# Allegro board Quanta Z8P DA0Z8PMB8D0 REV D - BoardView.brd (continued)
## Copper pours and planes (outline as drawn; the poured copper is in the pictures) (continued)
SY8288CSW on BOTTOM (solid shape): 141.53,80.83 141.56,80.81 141.58,80.78 141.58,80.16 141.78,80.16 141.78,80.78 141.79,80.81 141.83,80.83 141.97,80.83 142.02,80.78 142.02,79.89 141.87,79.74 141.87,79.15 142.68,78.34 144.23,78.34 144.39,78.19 144.39,76.03 143.98,75.62 139.56,75.62 139.18,76 139.18,79.05 139.33,79.2 140.14,79.2 140.3,79.35 140.3,79.71 141.41,80.83
TERM9 on TOP (solid shape): 41.85,109.03 41.85,106.68 38.98,103.81 27.01,103.81 26.69,104.13 26.69,105.41 27,105.72 31.15,105.72 31.17,105.7 31.18,105.69 31.53,105.43 31.89,105.67 31.9,105.69 31.95,105.72 32.4,105.72 32.45,105.69 32.45,105.67 32.81,105.43 33.16,105.67 33.17,105.69 33.22,105.72 37.33,105.72 37.64,106.03 37.64,106.15 37.64,106.16 37.64,108.57 37.64,108.57 37.64,108.77 38.13,109.27 41.6,109.27
TERM9 on BOTTOM (solid shape): 41.82,108.82 41.82,105.54 41.64,105.36 38.9,105.36 38.58,105.68 38.58,108.8 38.94,109.16 41.48,109.16
TP_PWR on BOTTOM (solid shape): 62.32,125.12 64.66,125.12 64.91,124.87 64.91,124.11 64.78,123.99 61.57,123.99 61.25,124.31 61.25,125.55 61.29,125.59 61.84,125.59
USBPWR1 on TOP (solid shape): 24.36,55.53 24.36,54.02 23.94,53.6 22.08,53.6 21.67,53.2 19.54,53.2 19.49,53.15 19.34,53.15 19.13,52.94 19.05,52.83 19.02,52.7 19.02,52.68 17.7,51.36 17.69,51.35 17.67,51.35 17.62,51.35 17.58,51.39 16.77,51.39 16.77,51.38 16.74,51.35 16.64,51.35 16.18,50.89 16.18,50.57 15.88,50.27 15.37,50.27 15.07,50.58 15.07,53.12 15.34,53.39 16.21,53.39 17.21,54.39 19.34,54.39 19.52,54.56 19.52,55.05 19.85,55.38 22.67,55.38 22.85,55.4 23,55.47 23.09,55.54 23.18,55.63 23.22,55.65 24.24,55.65
USBPWR1 on BOTTOM (solid shape): outline of 263 points within 14.93,48.78 23.42,58.01
USBPWR2 on TOP (solid shape): 226.88,18.55 226.88,17.53 226.88,17.51 226.86,17.49 226.86,16.87 226.84,16.84 226.81,16.82 225.08,16.82 224.43,16.17 224.43,15.48 223.67,14.72 221.95,14.72 221.68,14.99 221.68,15.61 221.71,15.68 221.78,15.71 222.16,16.09 221.78,16.47 221.71,16.5 221.68,16.57 221.68,16.89 221.73,17.04 221.73,17.19 221.73,18.09 221.91,18.27 222.66,18.27 222.69,18.24 224.21,18.24 225,19.03 226.4,19.03
USBPWR2 on BOTTOM (solid shape): 223.25,19.41 223.31,19.36 223.35,19.32 223.39,19.28 223.43,19.25 223.48,19.23 223.54,19.22 223.59,19.21 223.65,19.21 223.7,19.22 223.76,19.23 223.81,19.25 223.85,19.28 223.89,19.32 223.93,19.36 224.19,19.41 224.76,18.84 224.76,16.73 224.24,16.21 224.24,16.06 223.96,15.78 222.97,15.78 221.93,16.81 221.93,17.19 221.7,17.42 221.7,17.5 223.7,17.5 223.7,18.8 223.5,18.8 223.5,17.5 223.2,17.5 223.2,18.8 223,18.8 223,17.5 222.7,17.5 222.7,18.8 222.5,18.8 222.5,17.5 222.2,17.5 222.2,18.8 222,18.8 222,17.5 221.7,17.5 221.7,18.8 221.99,19.09 222.05,19.11 222.16,19.15 222.31,19.21 222.48,19.28 222.65,19.36 222.75,19.41
USBPWR2 on IN1 (solid shape): outline of 231 points within 214.77,15.96 224.83,18.21
VA1 on TOP (solid shape): 36.47,22.21 36.47,20.25 36.47,20.24 36.47,20.04 36.31,19.88 34.81,19.88 34.05,20.64 34.05,22.5 34.22,22.66 36.02,22.66
VA1 on TOP (solid shape): 233.29,44.49 233.29,43.27 232.93,42.92 231.7,42.92 231.23,42.45 231.23,39.37 231.03,39.17 229.6,39.17 228.69,38.26 223.3,38.26 222.72,38.84 222.72,42.31 222.8,42.44 222.88,42.59 223.05,42.75 228.59,42.75 228.97,43.13 228.97,44.02 229.58,44.63 233.15,44.63
VA1 on BOTTOM (solid shape): 233.3,44.47 233.3,40.1 232.52,39.32 229.75,39.32 228.51,38.08 223.35,38.08 222.52,38.92 222.52,42.04 222.55,42.08 222.61,42.15 222.66,42.23 222.79,42.42 222.9,42.62 222.92,42.64 222.95,42.65 224.83,42.65 225.06,42.42 225.15,42.42 225.17,42.4 227.34,42.4 227.37,42.42 227.52,42.42 229.88,44.79 232.99,44.79
VA1 on BOTTOM (solid shape): 199.92,40.45 199.99,40.42 200.02,40.35 200.07,40.14 200.24,39.97 200.24,39.94 200.24,39.79 200.24,39.79 200.24,38.47 200.22,38.46 199.77,38.46 199.43,38.8 198.33,38.8 198.16,38.64 198.16,38.59 198.14,38.57 198.14,37.57 198.15,37.55 198.16,37.53 198.46,37.23 198.46,36.76 198.36,36.66 197.57,36.66 197,37.23 197.01,37.65 197,37.69 197,38.27 197.01,38.31 197,38.38 197.02,38.42 197.06,38.43 197.44,38.81 197.06,39.2 197.02,39.21 197,39.25 197,39.79 197.67,40.45
VA1 on IN1 (solid shape): outline of 3494 points within 175.43,12.4 237.77,44.81
VA1 on IN2 (solid shape): outline of 2602 points within 33.8,12.34 181.14,26.17
VA2 on TOP (solid shape): outline of 139 points within 222.52,33.18 237.77,42.73
VA2 on IN2 (solid shape): 236.77,41.92 237.07,40.87 237.77,40.05 237.77,36.29 236.59,35.11 228.48,35.11 228.45,35.12 228.43,35.15 228.05,35.46 227.68,35.15 227.66,35.12 227.63,35.11 223.05,35.11 222.54,35.62 222.54,37.7 222.69,37.85 226.66,37.85 226.94,37.57 231.68,37.57 236.03,41.92
VA2 on IN3 (solid shape): 236.77,42.06 237.03,40.94 237.77,40.05 237.77,35.17 237.55,34.96 230.88,34.96 230.87,34.96 230.76,34.97 230.65,34.96 230.64,34.96 230.22,34.96 230.21,34.96 230.1,34.97 229.99,34.96 229.98,34.96 228.53,34.96 228.46,34.99 228.43,35.06 228.05,35.46 227.67,35.06 227.64,34.99 227.57,34.96 226.43,34.96 226.2,35.18 222.85,35.18 222.13,35.9 222.13,37.75 222.54,38.16 223.58,38.16 223.85,38.11 224.12,38.16 228.54,38.16 228.92,37.77 230.87,37.77 231.68,38.59 231.68,40.95 232.85,42.12 236.77,42.12
VOUT_BACKLIGHT on TOP (solid shape): 54.63,113.71 54.63,110.01 54.11,109.49 51.45,109.49 51.17,109.77 51.17,110.77 51.75,111.34 51.75,112.37 52.25,112.87 52.25,114.14 52.46,114.34 52.47,114.35 52.49,114.36 53.98,114.36
VOUT_BACKLIGHT on TOP (solid shape): 60.89,131.16 60.9,131.14 60.94,131.01 61.02,130.89 61.05,130.86 61.09,130.82 61.11,130.78 61.11,129.55 61.04,129.47 61.01,129.46 60.98,129.46 60.96,129.47 60.78,129.57 60.59,129.61 59.89,129.61 59.54,129.26 59.5,129.26 59.21,129.55 59.21,130.88 59.52,131.18 60.86,131.18
VOUT_BACKLIGHT on BOTTOM (solid shape): 61.07,130.78 61.07,129.85 61.06,129.82 61.02,129.8 60.26,129.8 60.26,129.6 61.02,129.6 61.06,129.59 61.07,129.55 61.07,129.37 61.02,129.32 61,129.3 60.98,129.3 60.26,129.3 60.26,129.29 58.93,129.29 58.76,129.46 58.76,130.65 59.04,130.93 60.92,130.93
VOUT_BACKLIGHT on IN3 (solid shape): outline of 367 points within 52.61,111.17 61.12,131.1
N20280006 on TOP (solid shape): 35.95,74.94 35.95,73.79 35.27,73.11 32.63,73.11 32.56,73.18 32.55,73.19 32.55,73.21 32.55,74.46 32.56,74.47 32.56,74.84 32.83,75.12 35.77,75.12
N22836684 on BOTTOM (solid shape): 126.83,103.92 127.72,103.92 127.82,103.81 127.82,103.33 127.65,103.15 125.87,103.15 125.79,103.23 125.79,103.92 125.92,104.04 126.71,104.04
N22836710 on BOTTOM (solid shape): 117.98,108.59 117.98,107.74 118.39,107.33 120.28,107.33 121.03,106.58 121.03,100.68 120.61,100.26 114.7,100.26 114.27,100.69 114.31,100.69 114.31,104.7 114.61,105.01 115.13,105.01 115.53,105.42 115.53,106.1 115.73,106.3 115.96,106.3 116.11,106.46 116.11,108.11 115.76,108.46 115.76,108.67 115.8,108.71 117.87,108.71
N22836724 on BOTTOM (solid shape): 130.08,106.74 130.08,106.1 130.29,105.9 131.48,105.9 131.84,106.25 132.29,106.25 132.43,106.14 132.44,106.12 132.45,106.1 132.45,101.63 132.17,101.35 128.41,101.35 128.18,101.58 128.18,102.44 128.41,102.67 129.5,102.67 129.6,102.77 129.6,105.03 129.02,105.62 129.02,106.35 129.03,106.38 129.07,106.4 129.73,106.4 129.73,106.64 129.07,106.64 129.03,106.66 129.02,106.69 129.02,106.85 129.03,106.87 129.05,106.88 129.07,106.89 129.93,106.89
N22841416 on BOTTOM (solid shape): 91.25,135.26 91.25,127.51 90.69,126.95 86.5,126.95 85.03,128.43 85.03,135.34 85.15,135.46 91.05,135.46
N22841457 on TOP (solid shape): 98.67,133.2 98.67,132.62 98.31,132.26 96.63,132.26 96.51,132.39 96.51,133.18 97.27,133.94 97.93,133.94
N22841539 on BOTTOM (solid shape): 75.45,134.52 75.45,133.74 75.75,133.43 77.2,133.43 77.71,132.92 77.71,131.2 77.33,130.82 74.08,130.82 73.93,130.66 69.55,130.66 69.43,130.81 69.25,130.89 68.54,131.6 68.54,132.31 68.54,132.31 68.54,133.91 68.87,134.24 72.6,134.24 72.96,134.6 74.05,134.6 74.46,135.01 74.97,135.01
N22946208 on BOTTOM (solid shape): 92.14,137.29 92.14,136.94 92.51,136.57 92.51,134.16 92.44,134.09 91.68,134.09 91.5,134.27 91.5,137.47 91.53,137.5 91.93,137.5
N22946324 on BOTTOM (solid shape): 92.92,129.55 92.92,128.38 92.75,128.2 91.76,128.2 91.63,128.33 91.63,129.52 91.81,129.7 92.77,129.7
N22946324 on BOTTOM (solid shape): 94.87,135.29 94.89,135.28 94.92,135.26 95.42,135.26 95.46,135.21 95.46,134.19 95.34,134.07 94.45,134.07 94.02,134.5 94.02,135.08 94.2,135.26 94.6,135.26 94.67,135.27 94.74,135.29
N22950763 on TOP (solid shape): 74.66,127.94 74.66,126.12 74.59,126.04 73.93,126.04 73.75,126.22 73.75,127.92 73.85,128.02 74.59,128.02
N22950767 on BOTTOM (solid shape): 79.39,134.52 79.39,133.63 79.16,133.41 78.09,133.41 77.81,133.69 76.01,133.69 75.73,133.96 75.73,134.52 75.83,134.63 79.28,134.63
N22950844 on BOTTOM (solid shape): 75.09,130.43 75.09,129.42 74.95,129.27 74.88,129.27 74.13,129.27 73.88,129.52 73.88,129.82 73.6,130.1 73.6,130.31 73.75,130.46 75.07,130.46
N23063584 on TOP (solid shape): 53.17,125.38 53.21,125.37 53.22,125.33 53.22,124.52 53.27,124.52 53.3,124.51 53.32,124.47 53.32,124.39 53.41,124.29 53.41,124.05 53.92,123.55 55.09,123.55 55.88,122.77 57.07,122.77 57.36,123.05 57.36,123.39 57.54,123.58 58.19,123.58 58.48,123.3 58.87,123.3 59,123.17 59,122.64 58.53,122.18 58.53,118.93 59.03,118.43 59.03,117.21 58.85,117.03 56.65,117.03 56.24,117.44 52.71,117.44 52.45,117.7 52.45,118.63 52.86,119.04 52.86,124.09 52.87,124.11 52.87,124.47 52.89,124.51 52.92,124.52 52.95,124.52 52.95,125.33 52.96,125.37 53,125.38
N25421357 on BOTTOM (solid shape): 200.24,37.76 200.24,35.74 200.12,35.62 198.71,35.62 198.61,35.72 198.61,37.27 198.26,37.62 198.26,38.52 198.34,38.6 199.4,38.6
N25421386 on TOP (solid shape): 62.23,19.87 62.23,16.57 61.99,16.33 61.47,16.33 61.25,16.11 61.25,14.18 60.72,13.64 54.27,13.64 53.55,14.36 53.55,17.43 54.06,17.94 58.17,17.94 60.27,20.04 62.06,20.04
N25421386 on BOTTOM (solid shape): 61.25,17.63 61.25,14.18 60.72,13.64 54.27,13.64 53.55,14.36 53.55,17.43 54.06,17.94 60.95,17.94
N25421433 on TOP (solid shape): 57.78,21.08 57.78,20.16 57.59,19.96 55.11,19.96 54.85,20.22 54.85,21.11 55,21.26 57.6,21.26
N25421470 on TOP (solid shape): 222.72,35.34 226.17,35.34 226.6,34.9 226.6,30.08 226.22,29.7 221.73,29.7 220.94,30.49 220.94,32.34 220.66,32.62 220.15,32.62 219.95,32.82 219.95,35.79 220.18,36.02 222.03,36.02
N25421528 on TOP (solid shape): 39.82,23.28 39.86,23.27 39.87,23.23 39.87,22.68 39.79,22.6 39.75,22.6 39.7,22.61 39.67,22.62 39.37,22.62 39.33,22.61 39.28,22.6 38.88,22.6 38.19,21.91 38.19,20.39 38.12,20.28 38.09,20.15 38.09,20.1 38.1,20.05 38.1,20.03 38.08,20.01 37.97,19.9 37.05,19.9 37.01,19.92 37,19.92 36.94,19.99 36.86,20.04 36.59,20.3 36.59,22.57 37.31,23.28
N25421533 on TOP (solid shape): 38.17,19.45 38.17,19.24 38.16,19.23 38.13,19.08 38.16,18.92 38.17,18.92 38.17,18.14 38.12,18.03 38.11,17.91 38.1,17.88 38.03,17.81 37.06,17.81 36.85,18.02 36.85,19.29 36.98,19.42 37.02,19.47 37.06,19.54 37.08,19.56 38.06,19.56
N27714931 on TOP (solid shape): 28.45,101.71 28.7,101.61 28.96,101.71 29.43,101.71 29.68,101.61 29.94,101.71 31.45,101.71 31.7,101.61 31.96,101.71 32.42,101.71 32.67,101.61 32.93,101.71 34.49,101.71 34.54,101.68 34.66,101.62 34.79,101.61 34.93,101.64 35.05,101.71 35.37,101.71 35.62,101.61 35.88,101.71 36.88,101.71 37.09,101.5 37.09,100.26 36.81,99.97 28.23,99.97 27.38,100.83 27.38,101.59 27.5,101.71
N27777984 on TOP (solid shape): 232.35,16.72 233.39,16.72 233.54,16.57 233.54,15.35 233.51,15.32 232.98,15.32 232.7,15.6 230.97,15.6 230.67,15.3 230.67,13.82 230.06,13.21 229.09,13.21 228.89,13.42 228.89,14.34 229.03,14.48 229.72,14.48 229.96,14.71 229.96,16.28 230.55,16.87 232.2,16.87
N27870072 on BOTTOM (solid shape): 100.54,129.44 100.54,128.55 100.29,128.3 98.94,128.3 98.77,128.48 98.77,129.44 98.89,129.57 100.42,129.57
N27871233 on BOTTOM (solid shape): 80.76,138.13 80.76,136.96 80.53,136.73 80.44,136.73 79.97,136.73 79.92,136.78 79.92,138.21 80.12,138.41 80.48,138.41
N28192386 on BOTTOM (solid shape): 62.73,129.92 62.83,129.92 62.95,129.8 62.95,128.92 62.6,128.57 61.52,128.57 61.29,128.8 61.29,129.72 61.3,129.73 61.3,130.15 61.71,130.56 62.09,130.56
N29271135 on TOP (solid shape): 57.96,116.39 57.96,115.34 57.57,114.95 57.05,114.95 56.85,114.75 56.85,113.1 56.67,112.93 56.01,112.93 55.38,113.55 55.38,114.48 56.46,115.56 56.46,116.43 56.6,116.58 57.77,116.58
N29271135 on TOP (solid shape): 61.2,123.5 61.2,122.47 61.08,122.36 60.89,122.36 60.84,122.36 60.54,122.36 60.5,122.36 60.24,122.36 60.24,122.4 60.09,122.68 59.79,122.75 59.77,122.75 59.58,122.93 59.58,123.48 59.71,123.6 59.72,123.6 59.86,123.57 60,123.6 60.01,123.6 61.1,123.6
N29271135 on IN1 (solid shape): 59.54,123.79 59.71,123.63 59.95,123.61 59.98,123.62 60.42,123.17 60.42,122.95 60.19,122.72 59.95,122.72 59.57,122.59 59.56,122.19 59.56,122.08 59.47,122.03 58.18,122.03 57.99,122.22 57.99,123.59 58.21,123.82 59.53,123.82
N29271139 on TOP (solid shape): 60.62,116.39 60.62,115.19 60.37,114.95 59.93,114.95 59.18,114.2 59.18,113.26 58.81,112.89 57.16,112.89 56.98,113.06 56.98,114.51 57.1,114.63 57.81,114.63 58.38,115.2 58.38,116.29 58.63,116.54 60.47,116.54
N29632396 on BOTTOM (solid shape): 110.73,110.44 110.73,109.81 110.73,109.6 110.63,109.5 110.19,109.5 109.49,108.8 109.21,108.8 109.21,110.07 108.84,110.07 108.84,108.8 108.56,108.8 108.56,110.38 109.05,110.88 110.29,110.88
N29634628 on BOTTOM (solid shape): 107.3,110.55 107.3,109.73 107.07,109.5 106.64,109.5 105.93,108.8 105.65,108.8 105.65,110.07 105.28,110.07 105.28,108.8 105,108.8 105,110.38 105.5,110.88 106.97,110.88
N29643478 on TOP (solid shape): 30.89,98.72 30.89,97.11 30.83,97.01 30.72,97.03 30.7,97.05 30.61,97.05 30.61,98.16 30.24,98.16 30.24,97.05 29.16,97.05 29.07,97.13 29.07,97.79 29.12,97.84 29.37,97.98 29.45,98.26 29.45,98.63 29.65,98.83 30.78,98.83
N30954436 on BOTTOM (solid shape): 147.56,48.27 147.56,46.21 147.55,46.18 147.51,46.16 146.7,46.16 146.29,45.75 146.25,45.73 146.21,45.75 146.16,45.8 146.16,46.39 146.01,46.54 144.1,46.54 143.5,47.15 141.59,47.15 141.34,47.4 141.34,47.78 141.46,47.91 143.52,47.91 144.03,48.42 147.41,48.42
N32459164 on BOTTOM (solid shape): 99,27.43 99,25.41 98.83,25.23 98.18,25.23 97.97,25.43 97.97,27.46 98.16,27.64 98.79,27.64
N35788414 on BOTTOM (solid shape): 133.11,49.89 133.11,48.42 133.26,48.27 134.6,48.27 134.62,48.26 134.64,48.25 134.85,48.01 136.84,48.01 137.07,47.78 137.07,47.43 136.79,47.15 132.07,47.15 131.99,47.22 131.99,48.37 131.58,48.78 131.58,49.33 131.59,49.34 131.63,49.51 131.59,49.69 131.58,49.7 131.58,49.92 131.61,49.94 133.06,49.94
N36056010 on TOP (solid shape): 45.45,81.18 45.45,77.48 45.44,77.47 45.41,77.31 45.44,77.16 45.45,77.15 45.45,75.35 44.93,74.84 42.53,74.84 42.17,75.2 42.17,81.08 42.42,81.33 45.29,81.33
N36056010 on BOTTOM (solid shape): 44.94,76.15 44.94,75.6 46.18,74.36 47.83,74.36 47.88,74.31 47.88,73.52 47.8,73.44 45.78,73.44 45.73,73.39 44.5,73.39 44.18,73.59 43.83,73.47 43.75,73.44 43.68,73.47 43.41,73.59 43.12,73.51 43.12,76.31 43.22,76.41 44.69,76.41
N36057265 on BOTTOM (solid shape): 127.7,88.3 127.7,85.55 128.38,84.87 128.38,83.98 128.66,83.7 128.66,81.44 128.65,81.41 128.61,81.39 128.05,81.39 127.13,80.47 126.02,80.47 125.92,80.57 125.92,88.37 126.07,88.52 127.47,88.52
N36057285 on BOTTOM (solid shape): 129.15,91.06 129.15,90.92 129.2,90.87 129.23,90.83 129.25,90.79 129.45,90.44 129.86,90.48 130.77,90.48 130.92,90.33 130.92,89.51 130.52,89.11 130.52,87.53 130.47,87.48 129.98,87.48 129.75,87.71 129.75,89.29 129.35,89.69 128.36,89.69 127.95,90.1 127.95,90.59 128.52,91.17 129.04,91.17

Small or netless copper shapes (teardrops, artwork), in the pictures only: 50 on TOP, 10 on BOTTOM, 11 on IN1, 80 on IN2, 3 on IN3

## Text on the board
Ref Des/Silkscreen Bottom: REV:D | DA0Z8PMB8D0 | MODEL:Z8P
User.Comments: PARTITION_2 | 30.0x32.0 | 40.0x43.0 | 239.3 | 141.8 | SCALE | 1/1
Ref Des/Silkscreen Top: DA0Z8PMB8D0 | REV:D
BODY_CENTER: OUT LINE
User.6: SCALE | 1/1
User.8: SCALE | 1/1
User.12: +5V_S5 | +VNN | +VCC_VCCGI | +VCC_1.05V_IO | GND | +VIN | ADOGND
User.24: OUT LINE
User.26: ADOGND | GND
User.27: ADOGND | GND
User.30: REV:A-8
User.45: XY-Check acute:Dec 05 12:59:44 2016 | XY-Check cline width:Dec 05 13:08:51 2016 | XY-Create nettxt:Nov 29 14:47:00 2016 | XY-Create plane:Dec 05 11:54:23 2016 | XY-Cross plane-BOTTOM-SGND1:Dec 05 13:04:05 2016 | XY-Cross plane-IN1-SGND:Dec 05 13:03:57 2016 | XY-Cross plane-IN1-SVCC:Dec 05 13:03:54 2016 | XY-Cross plane-IN2-SVCC:Dec 05 13:04:00 2016 | XY-Cross plane-IN3-SGND1:Dec 05 13:04:02 2016 | XY-Cross plane-TOP-SGND:Dec 05 13:03:46 2016 | XY-Dxf to pin check:Dec 05 12:54:40 2016 | XY-Etch cross-IN2-IN3:Dec 05 13:04:00 2016 | XY-Etch ref-BOTTOM-SGND1:Dec 05 13:04:10 2016 | XY-Etch ref-IN1-SGND:Dec 05 13:03:59 2016 | XY-Etch ref-IN1-SVCC:Dec 05 13:03:57 2016 | XY-Etch ref-IN2-SVCC:Dec 05 13:04:02 2016 | XY-Etch ref-IN3-SGND1:Dec 05 13:04:05 2016 | XY-Etch ref-TOP-SGND:Dec 05 13:03:54 2016 | XY-Excess check:Dec 05 10:38:39 2016 | XY-Mask check:Dec 05 13:16:37 2016 | XY-Outline check:Dec 05 13:15:27 2016 | XY-PadStack_Check:Dec 05 12:49:56 2016 | XY-Plane net check:Dec 05 12:57:23 2016 | XY-Prop check:Dec 05 13:03:44 2016 | XY-TP check:Dec 05 12:50:01 2016 | XY-shape min check:Dec 05 12:45:00 2016 | XY-via check:Dec 05 13:10:32 2016 | PT_TOP | PT_BOT | FIGURE | TYPE | Oblong | Circle | SIZE | 43.0x20.0 | 55.0x20.0 | 59.0x31.0 | 63.0x32.0 | 75.0x31.0 | 91.0x43.0 | 102.0x31.0 | 10.0 | 12.0 | 14.0 | 18.0 | 22.0 | 24.0 | 31.0 | 35.0 | 40.0 | 94.0 | 95.0 | 126.0 | 138.0 | 165.0 | 220.0 | 28.0 | 32.0 | 33.0 | 43.0 | 47.0 | 48.0 | 67.0 | 68.0 | 122.0 | 156.0 | DRILL CHART: TOP to BOTTOM | ALL UNITS ARE IN MILS | PLATED | NON-PLATED | ROTATION | 0.000 | 90.000 | - | QTY | 2 | 4 | 1 | 18 | 2979 | 9 | 718 | 12 | 19 | 64 | 8 | 3 | 3858 | TOTAL HOLES:
